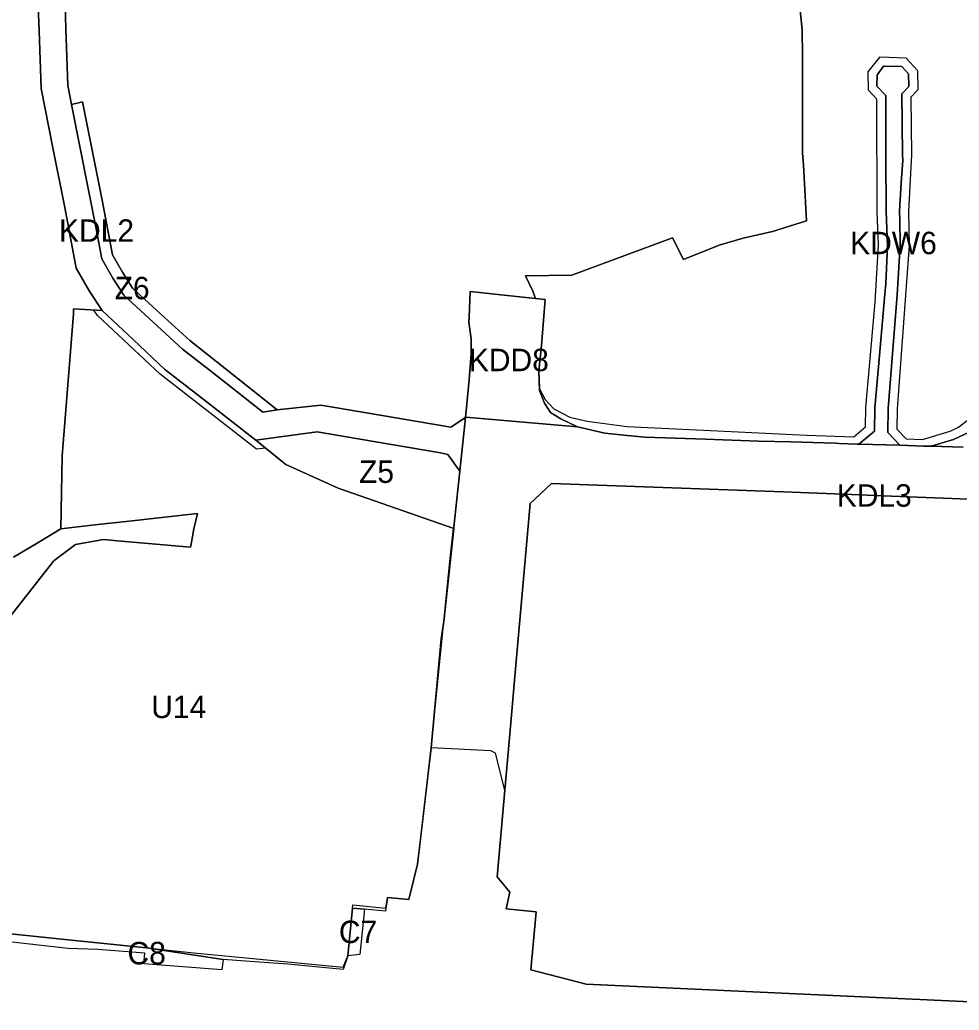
# Model space of a CAD drawing. Extents: x 7428841 to 7433518, y 5545054 to 5546840.
# Drawn here: x 7429514.3 to 7429933, y 5545108.1 to 5545549.4 of the extents above; entities that cross this region are included whole.
import ezdxf

# ---------------------------------------------------------------- set-up
doc = ezdxf.new("R2010")
doc.units = 0
for name, color, linetype in [('linie_rozgraniczajace', 7, 'Continuous'), ('linie_zabudowy_nieprzekraczalne', 7, 'Continuous'), ('oznaczenia_przeznaczen', 7, 'Continuous')]:
    doc.layers.add(name, color=color, linetype=linetype)

msp = doc.modelspace()

# ---------------------------------------------------------------- linework, layer by layer
at = {"layer": 'linie_rozgraniczajace'}
for points in [[(7429508.94, 5545604.73), (7429517.67, 5545612.86), (7429524.31, 5545610.01), (7429521.77, 5545584.17), (7429521.99, 5545570.36), (7429522.9, 5545544.57), (7429523.81, 5545518.79), (7429529.09, 5545492.31), (7429534.36, 5545465.82), (7429539.51, 5545438.69), (7429545.49, 5545428.17), (7429551.07, 5545419.83), (7429538.24, 5545420.68), (7429538.25, 5545418.47), (7429533.26, 5545355.15), (7429532.6, 5545322.55), (7429522.06, 5545316.24), (7429511.53, 5545309.92)], [(7429533.78, 5545583.68), (7429534.88, 5545545.43), (7429535.77, 5545520.18), (7429537.45, 5545511.74), (7429548.53, 5545455.5), (7429550.93, 5545442.89), (7429555.79, 5545434.34), (7429560.63, 5545426.66), (7429586.86, 5545402.71), (7429600.11, 5545392.35), (7429613.35, 5545381.98), (7429622.6, 5545374.63), (7429629, 5545375.61), (7429648.5, 5545377.75), (7429667.05, 5545374.58), (7429706.44, 5545367.85), (7429712.9, 5545372.24), (7429710.38, 5545348.23), (7429705.05, 5545355.7), (7429701.77, 5545356.47), (7429665.16, 5545362.73), (7429646.86, 5545365.86), (7429619.51, 5545362.05), (7429609.36, 5545369.91), (7429593.93, 5545381.98), (7429578.86, 5545393.73), (7429564.96, 5545406.78), (7429551.07, 5545419.83), (7429545.49, 5545428.17), (7429539.51, 5545438.69), (7429534.36, 5545465.82), (7429529.09, 5545492.31), (7429523.81, 5545518.79), (7429522.9, 5545544.57), (7429521.99, 5545570.36)], [(7429860.76, 5545566.76), (7429863.08, 5545544.91), (7429863.16, 5545533.33), (7429863.2, 5545528.41), (7429863.22, 5545494.33), (7429863.22, 5545490.2), (7429863.55, 5545484.71), (7429863.88, 5545479.22), (7429864.91, 5545459.87), (7429849.75, 5545455.02), (7429836.78, 5545452.15), (7429826.09, 5545448.93), (7429810.16, 5545442.63), (7429805.23, 5545452.33), (7429760.43, 5545435.7), (7429739.67, 5545435.38), (7429743.03, 5545428.44), (7429744.16, 5545425.24), (7429727.38, 5545427.01), (7429717.91, 5545427.99), (7429715.08, 5545428.29), (7429714.56, 5545416.91), (7429714.46, 5545414.71), (7429715.45, 5545407.3), (7429715.47, 5545403.93), (7429715.48, 5545400.55), (7429715.07, 5545394.76), (7429714.65, 5545388.97), (7429712.9, 5545372.24), (7429706.44, 5545367.85), (7429667.05, 5545374.58), (7429648.5, 5545377.75), (7429629, 5545375.61), (7429605.87, 5545393.99), (7429590.09, 5545406.53), (7429577.04, 5545418.44), (7429564.49, 5545429.9), (7429560.08, 5545436.91), (7429555.68, 5545444.64), (7429551.05, 5545469.07), (7429542.21, 5545512.9), (7429537.45, 5545511.74), (7429535.77, 5545520.18), (7429534.88, 5545545.43), (7429533.78, 5545583.68)], [(7429739.67, 5545435.38), (7429760.43, 5545435.7), (7429805.23, 5545452.33), (7429810.16, 5545442.63), (7429826.09, 5545448.93), (7429836.78, 5545452.15), (7429849.75, 5545455.02), (7429864.91, 5545459.87), (7429863.88, 5545479.22), (7429863.55, 5545484.71), (7429863.22, 5545490.2), (7429863.22, 5545494.33), (7429863.2, 5545528.41), (7429863.16, 5545533.33), (7429863.08, 5545544.91), (7429860.76, 5545566.76)], [(7429907.8, 5545486.79), (7429907.76, 5545489.42), (7429907.43, 5545516.5), (7429910.48, 5545519.77), (7429910.45, 5545525.32), (7429907.41, 5545528.58), (7429899.62, 5545528.83), (7429899.21, 5545528.84), (7429896.65, 5545525.12), (7429896.49, 5545524.9), (7429896.23, 5545519.9), (7429900.28, 5545515.72), (7429900.28, 5545488.74), (7429900.42, 5545464.01), (7429901.06, 5545448.69), (7429900.3, 5545431.75), (7429899.72, 5545425.58), (7429899.11, 5545418.77), (7429897.41, 5545399.86), (7429895.34, 5545376.45), (7429895.21, 5545366.14), (7429888.3, 5545360.38), (7429887.55, 5545360.39), (7429879.43, 5545360.66), (7429877.93, 5545360.71), (7429867.74, 5545361.03), (7429857.99, 5545361.33), (7429843.48, 5545361.72), (7429819.87, 5545362.54), (7429792.94, 5545363.38), (7429785.06, 5545364.15), (7429775.01, 5545365.15), (7429762.84, 5545368.03), (7429755.39, 5545371.54), (7429750.89, 5545374.36), (7429748.18, 5545378.6), (7429745.96, 5545384.29), (7429745.65, 5545392.84), (7429746.79, 5545404.23), (7429747.82, 5545417.35), (7429748.48, 5545424.78), (7429744.16, 5545425.24), (7429743.03, 5545428.44), (7429739.67, 5545435.38)], [(7429943.77, 5545368.69), (7429930.43, 5545362.4), (7429920.54, 5545359.36), (7429917.1, 5545359.47), (7429906.5, 5545359.81), (7429901.2, 5545365.5), (7429901.34, 5545376.18), (7429905.34, 5545426.82), (7429906.71, 5545448.93), (7429906.55, 5545460.36), (7429906.42, 5545464.15), (7429907.09, 5545476.78), (7429907.8, 5545486.79)], [(7429489, 5545256.77), (7429529.42, 5545308.25), (7429529.69, 5545308.54), (7429539.13, 5545315.66), (7429551.62, 5545317.82), (7429553.44, 5545317.66), (7429557.79, 5545317.27), (7429564.77, 5545316.64), (7429590.39, 5545314.35), (7429590.65, 5545315.77), (7429591.88, 5545322.65), (7429593.54, 5545329.41), (7429593.5, 5545329.4), (7429563.05, 5545325.98), (7429547.8, 5545324.3), (7429532.6, 5545322.55), (7429533.26, 5545355.15), (7429538.25, 5545418.47), (7429538.24, 5545420.68), (7429551.07, 5545419.83), (7429564.96, 5545406.78), (7429578.86, 5545393.73), (7429593.93, 5545381.98), (7429609.36, 5545369.91), (7429619.51, 5545362.05), (7429632.09, 5545351.81), (7429632.83, 5545351.33), (7429656.21, 5545340.65), (7429707.71, 5545322.76), (7429703.31, 5545281.3), (7429702.16, 5545273.61), (7429697.65, 5545224.99), (7429691.63, 5545173.11), (7429687.64, 5545157.43), (7429678.2, 5545158.28), (7429677.37, 5545152.14), (7429667.89, 5545153.16), (7429662.59, 5545153.5), (7429660.52, 5545132.36), (7429658.41, 5545126.16), (7429633.85, 5545128.55), (7429618.99, 5545129.63), (7429604.96, 5545130.73), (7429570.76, 5545135.84), (7429535.89, 5545139.5), (7429505.84, 5545142.57)], [(7429994.98, 5545333.61), (7429895.15, 5545337.47), (7429888.87, 5545337.71), (7429854.74, 5545339.04), (7429751.31, 5545342.75), (7429748.26, 5545339.9), (7429741.75, 5545333.86), (7429739.98, 5545313.68), (7429737.63, 5545286.91), (7429735.28, 5545260.15), (7429733.04, 5545234.55), (7429730.55, 5545206.18), (7429726.4, 5545222.64), (7429724.33, 5545223.71), (7429697.65, 5545224.99), (7429702.16, 5545273.61), (7429703.31, 5545281.3), (7429707.71, 5545322.76), (7429707.77, 5545323.27), (7429710.38, 5545348.23), (7429712.9, 5545372.24), (7429713.02, 5545372.32), (7429762.84, 5545368.03), (7429775.01, 5545365.15), (7429785.06, 5545364.15), (7429792.94, 5545363.38), (7429819.87, 5545362.54), (7429843.48, 5545361.72), (7429857.99, 5545361.33), (7429867.74, 5545361.03), (7429877.93, 5545360.71), (7429879.43, 5545360.66), (7429887.55, 5545360.39), (7429888.3, 5545360.38), (7429906.5, 5545359.81), (7429917.1, 5545359.47), (7429920.54, 5545359.36), (7429934.73, 5545358.92)], [(7429934.73, 5545358.92), (7429920.54, 5545359.36), (7429930.43, 5545362.4), (7429943.77, 5545368.69)], [(7429967.17, 5545110.46), (7429766.71, 5545119.71), (7429742.07, 5545126.13), (7429744.53, 5545151.94), (7429731.08, 5545153.27), (7429732.75, 5545160.67), (7429727.14, 5545167.45), (7429730.55, 5545206.18), (7429733.04, 5545234.55), (7429735.28, 5545260.15), (7429737.63, 5545286.91), (7429739.98, 5545313.68), (7429741.75, 5545333.86), (7429748.26, 5545339.9), (7429751.31, 5545342.75), (7429854.74, 5545339.04), (7429888.87, 5545337.71), (7429895.15, 5545337.47), (7429994.98, 5545333.61)], [(7429511.53, 5545309.92), (7429522.06, 5545316.24), (7429532.6, 5545322.55), (7429547.8, 5545324.3), (7429563.05, 5545325.98), (7429593.5, 5545329.4), (7429593.54, 5545329.41), (7429591.88, 5545322.65), (7429590.65, 5545315.77), (7429590.39, 5545314.35), (7429564.77, 5545316.64), (7429557.79, 5545317.27), (7429553.44, 5545317.66), (7429551.62, 5545317.82), (7429539.13, 5545315.66), (7429529.69, 5545308.54), (7429529.42, 5545308.25), (7429489, 5545256.77)]]:
    msp.add_lwpolyline(points, dxfattribs=at)
for points in [[(7429888.3, 5545360.38), (7429895.21, 5545366.14), (7429895.34, 5545376.45), (7429897.41, 5545399.86), (7429899.11, 5545418.77), (7429899.72, 5545425.58), (7429900.3, 5545431.75), (7429901.06, 5545448.69), (7429900.42, 5545464.01), (7429900.28, 5545488.74), (7429900.28, 5545515.72), (7429896.23, 5545519.9), (7429896.49, 5545524.9), (7429896.65, 5545525.12), (7429899.21, 5545528.84), (7429899.62, 5545528.83), (7429907.41, 5545528.58), (7429910.45, 5545525.32), (7429910.48, 5545519.77), (7429907.43, 5545516.5), (7429907.76, 5545489.42), (7429907.8, 5545486.79), (7429907.09, 5545476.78), (7429906.42, 5545464.15), (7429906.55, 5545460.36), (7429906.71, 5545448.93), (7429905.34, 5545426.82), (7429901.34, 5545376.18), (7429901.2, 5545365.5), (7429906.5, 5545359.81)], [(7429537.45, 5545511.74), (7429542.21, 5545512.9), (7429551.05, 5545469.07), (7429555.68, 5545444.64), (7429560.08, 5545436.91), (7429564.49, 5545429.9), (7429577.04, 5545418.44), (7429590.09, 5545406.53), (7429605.87, 5545393.99), (7429629, 5545375.61), (7429622.6, 5545374.63), (7429613.35, 5545381.98), (7429600.11, 5545392.35), (7429586.86, 5545402.71), (7429560.63, 5545426.66), (7429555.79, 5545434.34), (7429550.93, 5545442.89), (7429548.53, 5545455.5)], [(7429712.9, 5545372.24), (7429714.65, 5545388.97), (7429715.07, 5545394.76), (7429715.48, 5545400.55), (7429715.47, 5545403.93), (7429715.45, 5545407.3), (7429714.46, 5545414.71), (7429714.56, 5545416.91), (7429715.08, 5545428.29), (7429717.91, 5545427.99), (7429727.38, 5545427.01), (7429744.16, 5545425.24), (7429748.48, 5545424.78), (7429747.82, 5545417.35), (7429746.79, 5545404.23), (7429745.65, 5545392.84), (7429745.96, 5545384.29), (7429748.18, 5545378.6), (7429750.89, 5545374.36), (7429755.39, 5545371.54), (7429762.84, 5545368.03), (7429713.02, 5545372.32)], [(7429619.51, 5545362.05), (7429646.86, 5545365.86), (7429665.16, 5545362.73), (7429701.77, 5545356.47), (7429705.05, 5545355.7), (7429710.38, 5545348.23), (7429707.77, 5545323.27), (7429707.71, 5545322.76), (7429656.21, 5545340.65), (7429632.83, 5545351.33), (7429632.09, 5545351.81)], [(7429660.52, 5545132.36), (7429662.59, 5545153.5), (7429667.89, 5545153.16), (7429665.85, 5545132.86)], [(7429505.51, 5545138.97), (7429505.84, 5545142.57), (7429535.89, 5545139.5), (7429570.76, 5545135.84), (7429604.96, 5545130.73), (7429604.42, 5545126.1), (7429569.55, 5545128.79), (7429569.99, 5545133.5), (7429549.13, 5545135.14), (7429535.93, 5545135.57)]]:
    msp.add_lwpolyline(points, close=True, dxfattribs=at)
at = {"layer": 'linie_zabudowy_nieprzekraczalne'}
for points in [[(7429916.68, 5545362.36), (7429928.99, 5545366.14), (7429932.75, 5545367.92), (7429937.28, 5545371.39), (7429941.65, 5545374.15), (7429950.43, 5545378.73), (7429964.76, 5545385.17), (7429979.65, 5545392.39), (7430016.19, 5545408.83), (7430052.74, 5545425.27), (7430069.56, 5545435.44), (7430085.37, 5545448.31), (7430094.13, 5545454.32), (7430121.89, 5545469.39), (7430135.65, 5545477.49), (7430147.49, 5545486.06), (7430186.38, 5545518.29), (7430212.67, 5545540.14), (7430212.85, 5545543.36)], [(7429885.99, 5545363.57), (7429891.21, 5545368.04), (7429891.35, 5545376.66), (7429895.5, 5545423.56), (7429897.06, 5545449.09), (7429896.42, 5545463.92), (7429896.29, 5545514.13), (7429892.56, 5545518.1), (7429892.48, 5545526.28), (7429897.74, 5545532.89), (7429909.19, 5545532.53), (7429914.44, 5545526.91), (7429914.48, 5545518.2), (7429911.45, 5545514.95), (7429911.77, 5545489.33), (7429910.42, 5545464.08), (7429910.72, 5545448.82), (7429905.34, 5545376), (7429905.22, 5545367.05), (7429909.31, 5545362.72)], [(7429744.16, 5545425.24), (7429748.48, 5545424.78), (7429746.79, 5545404.23), (7429745.65, 5545392.84), (7429745.94, 5545384.97), (7429748.43, 5545380.22), (7429752.38, 5545376.09), (7429759.49, 5545372.29), (7429767.15, 5545370.56), (7429785.01, 5545368.21), (7429834.54, 5545365.76), (7429864.96, 5545364.34), (7429886.09, 5545363.64), (7429886.09, 5545363.64)], [(7429623.88, 5545358.56), (7429619.78, 5545358.02), (7429576.91, 5545391.45), (7429549.01, 5545417.64), (7429547.31, 5545419.99)], [(7429909.31, 5545362.72), (7429916.68, 5545362.36)], [(7430141.2, 5545328.03), (7430125.01, 5545328.63), (7430068.54, 5545330.76), (7429994.98, 5545333.61), (7429945.06, 5545335.54), (7429895.15, 5545337.47), (7429871.81, 5545338.38), (7429854.74, 5545339.04), (7429803.03, 5545340.9), (7429751.31, 5545342.75), (7429741.75, 5545333.86), (7429738.51, 5545297), (7429735.28, 5545260.15), (7429733.04, 5545234.55), (7429730.55, 5545206.18)], [(7429697.65, 5545224.99), (7429706.27, 5545310.92), (7429707.57, 5545322.77)], [(7429677.51, 5545153.62), (7429678.2, 5545158.28), (7429687.64, 5545157.43), (7429691.63, 5545173.11), (7429693.1, 5545185.38), (7429697.65, 5545224.99)], [(7429730.55, 5545206.18), (7429727.14, 5545167.45), (7429732.75, 5545160.67), (7429731.08, 5545153.27), (7429744.53, 5545151.94), (7429742.07, 5545126.13), (7429766.71, 5545119.71), (7429967.17, 5545110.46), (7430010.97, 5545109.36), (7430045.95, 5545108.72), (7430080.94, 5545108.08), (7430087.61, 5545109.15), (7430101.91, 5545108.31), (7430165.88, 5545119.44), (7430182.29, 5545142.3), (7430188.19, 5545137.46), (7430203.58, 5545142.22), (7430205.95, 5545138.43), (7430209.63, 5545136.23), (7430220.88, 5545133.1), (7430233.75, 5545137), (7430246.62, 5545140.9), (7430244.43, 5545157.62), (7430265.18, 5545162.82)], [(7429510.81, 5545142.04), (7429535.89, 5545139.5), (7429570.76, 5545135.84), (7429593.38, 5545133.47), (7429658.51, 5545127.18), (7429660.52, 5545132.36), (7429662.59, 5545153.5), (7429662.75, 5545155.06), (7429677.51, 5545153.62)]]:
    msp.add_lwpolyline(points, dxfattribs=at)

# ---------------------------------------------------------------- texts
at = {"layer": 'oznaczenia_przeznaczen'}
for s, p in [('KDL2', (7429531.81, 5545450.5)), ('KDW6', (7429884.38, 5545444.98)), ('Z6', (7429556.58, 5545424.9)), ('KDD8', (7429714.45, 5545392.84)), ('Z5', (7429665.51, 5545343.05)), ('KDL3', (7429878.42, 5545332.47)), ('U14', (7429572.9, 5545238.26)), ('C7', (7429656.54, 5545137.99)), ('C8', (7429562.33, 5545128.5))]:
    msp.add_text(s, height=10, dxfattribs=at).set_placement(p)

doc.saveas('drawing.dxf')
